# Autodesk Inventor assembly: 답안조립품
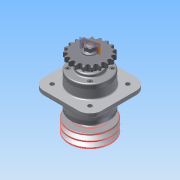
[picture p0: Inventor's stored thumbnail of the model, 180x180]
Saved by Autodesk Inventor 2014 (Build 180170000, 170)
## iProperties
Created: 2015-09
Part Number: 답안조립품
Document SubType Name: Assembly
Designer: study
Author: study
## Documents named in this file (12)
- C:\Users\study\Desktop\450909V1010\답안조립품.iam
- C:\Users\study\Desktop\450909V1010\1-본체.ipt
- C:\Users\study\Desktop\450909V1010\6-베어링 6206.ipt
- C:\Users\study\Desktop\450909V1010\3-축.ipt
- C:\Users\study\Desktop\450909V1010\11-키 6x6.ipt
- C:\Users\study\Desktop\450909V1010\2-커버.ipt
- C:\Users\study\Desktop\450909V1010\8-오일실 30x42.ipt
- C:\Users\study\Desktop\450909V1010\7-부시.ipt
- C:\Users\study\Desktop\450909V1010\4-V벨트풀리.ipt
- C:\Users\study\Desktop\450909V1010\5-체인 스프로킷.ipt
- C:\Users\study\Desktop\450909V1010\9-M16-너트.ipt
- C:\Users\study\Desktop\450909V1010\10-M6.ipt
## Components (23 placed, 11 different names)
1. 1-본체:1
2. 6-베어링 6206:1
3. 6-베어링 6206:2
4. 3-축:1 — 각도:1, 각도:2
5. 11-키 6x6:1 — 각도:1, 각도:4
6. 11-키 6x6:2 — 각도:2, 각도:3
7. 2-커버:1
8. 8-8-오일실 30x42:1
9. 2-커버:2
10. 8-8-오일실 30x42:2
11. 7-부시:1
12. 4-V벨트풀리:1 — 각도:3
13. 5-체인 스프로킷:1 — 각도:4
14. 9-M16 너트:1
15. 9-M16 너트:2
16. 10-M6:2
17. 10-M6:3
18. 10-M6:4
19. 10-M6:5
20. 10-M6:1
21. 10-M6:6
22. 10-M6:7
23. 10-M6:8
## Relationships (4: Angle 4)
- 각도:1 [Angle]: 3-축:1 ↔ 11-키 6x6:1
- 각도:2 [Angle]: 3-축:1 ↔ 11-키 6x6:2
- 각도:3 [Angle]: 11-키 6x6:2 ↔ 4-V벨트풀리:1
- 각도:4 [Angle]: 11-키 6x6:1 ↔ 5-체인 스프로킷:1
